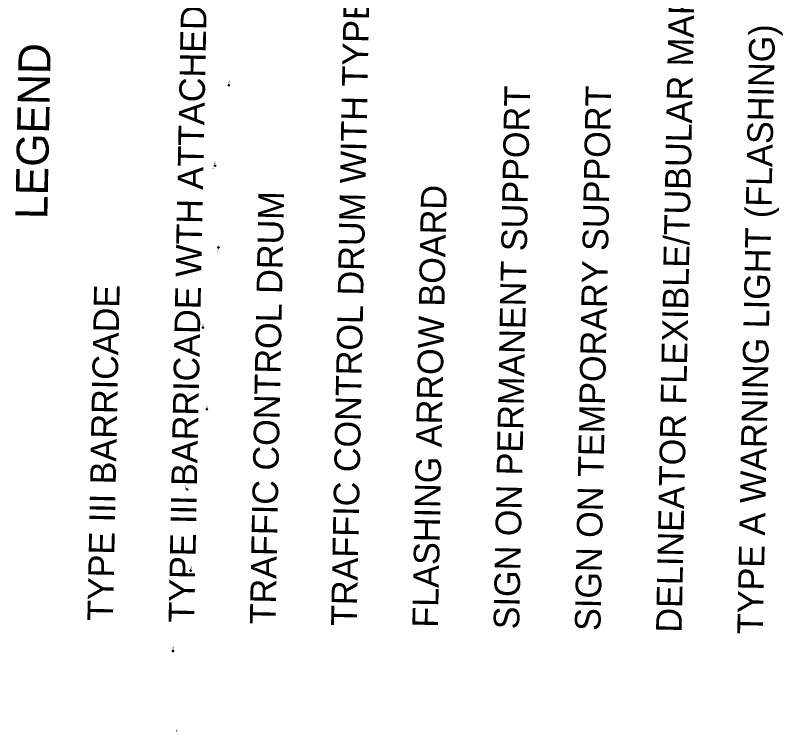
# Model space of a CAD drawing. Extents: x 345549 to 379569, y 127949 to 230467.
# Drawn here: x 358252 to 363918, y 165871 to 171164 of the extents above; entities that cross this region are included whole.
import ezdxf

# ---------------------------------------------------------------- set-up
doc = ezdxf.new("R2010")
doc.units = 0
for name, color, linetype in [('E_SOIL_BORE1 [KAPUR_CADDS_LEVELS]', 7, 'Continuous'), ('E_SOIL_BORE2 [KAPUR_CADDS_LEVELS]', 7, 'Continuous'), ('P_MARK', 7, 'Continuous'), ('P_TC_Text', 7, 'Continuous')]:
    doc.layers.add(name, color=color, linetype=linetype)

msp = doc.modelspace()

# ---------------------------------------------------------------- linework, layer by layer
at = {"layer": 'P_MARK'}
for p, q in [((359823, 170647.5), (359833, 170647.5)), ((359828, 170652.5), (359828, 170642.5)), ((359721.4, 170053), (359731.4, 170053)), ((359726.4, 170058), (359726.4, 170048)), ((359746.5, 169449.5), (359756.5, 169449.5)), ((359751.5, 169454.5), (359751.5, 169444.5)), ((359631.8, 168856.8), (359641.8, 168856.8)), ((359636.8, 168861.8), (359636.8, 168851.8)), ((359660.4, 168252.8), (359670.4, 168252.8)), ((359665.4, 168257.8), (359665.4, 168247.8)), ((359515.3, 167661.3), (359525.3, 167661.3)), ((359520.3, 167666.3), (359520.3, 167656.3)), ((359541.8, 167060.1), (359551.8, 167060.1)), ((359546.8, 167065.1), (359546.8, 167055.1)), ((359415, 166471.5), (359415, 166461.5)), ((359410, 166466.5), (359420, 166466.5))]:
    msp.add_line(p, q, dxfattribs=at)
for centre in [(359828, 170647.5), (359726.4, 170053), (359751.5, 169449.5), (359636.8, 168856.8), (359665.4, 168252.8), (359520.3, 167661.3), (359546.8, 167060.1), (359415, 166466.5)]:
    msp.add_circle(centre, 5, dxfattribs=at)
for centre, radius, start, end in [((359828, 170647.5), 4.5, 89.9869, 179.9869), ((359828, 170647.5), 4, 89.9869, 179.9869), ((359828, 170647.5), 3.5, 89.9869, 179.9869), ((359828, 170647.5), 3, 89.9869, 179.9869), ((359828, 170647.5), 2.5, 89.9869, 179.9869), ((359828, 170647.5), 2, 89.9869, 179.9869), ((359828, 170647.5), 1.5, 89.9869, 179.9869), ((359828, 170647.5), 1, 89.9869, 179.9869), ((359828, 170647.5), 0.5, 89.9869, 179.9869), ((359828, 170647.5), 4.5, 269.9869, 359.9869), ((359828, 170647.5), 4, 269.9869, 359.9869), ((359828, 170647.5), 3.5, 269.9869, 359.9869), ((359828, 170647.5), 3, 269.9869, 359.9869), ((359828, 170647.5), 2.5, 269.9869, 359.9869), ((359828, 170647.5), 2, 269.9869, 359.9869), ((359828, 170647.5), 1.5, 269.9869, 359.9869), ((359828, 170647.5), 1, 269.9869, 359.9869), ((359828, 170647.5), 0.5, 269.9869, 359.9869), ((359726.4, 170053), 4.5, 89.9869, 179.9869), ((359726.4, 170053), 4, 89.9869, 179.9869), ((359726.4, 170053), 3.5, 89.9869, 179.9869), ((359726.4, 170053), 3, 89.9869, 179.9869), ((359726.4, 170053), 2.5, 89.9869, 179.9869), ((359726.4, 170053), 2, 89.9869, 179.9869), ((359726.4, 170053), 1.5, 89.9869, 179.9869), ((359726.4, 170053), 1, 89.9869, 179.9869), ((359726.4, 170053), 0.5, 89.9869, 179.9869), ((359726.4, 170053), 4.5, 269.9869, 359.9869), ((359726.4, 170053), 4, 269.9869, 359.9869), ((359726.4, 170053), 3.5, 269.9869, 359.9869), ((359726.4, 170053), 3, 269.9869, 359.9869), ((359726.4, 170053), 2.5, 269.9869, 359.9869), ((359726.4, 170053), 2, 269.9869, 359.9869), ((359726.4, 170053), 1.5, 269.9869, 359.9869), ((359726.4, 170053), 1, 269.9869, 359.9869), ((359726.4, 170053), 0.5, 269.9869, 359.9869), ((359751.5, 169449.5), 4.5, 89.9869, 179.9869), ((359751.5, 169449.5), 4, 89.9869, 179.9869), ((359751.5, 169449.5), 3.5, 89.9869, 179.9869), ((359751.5, 169449.5), 3, 89.9869, 179.9869), ((359751.5, 169449.5), 2.5, 89.9869, 179.9869), ((359751.5, 169449.5), 2, 89.9869, 179.9869), ((359751.5, 169449.5), 1.5, 89.9869, 179.9869), ((359751.5, 169449.5), 1, 89.9869, 179.9869), ((359751.5, 169449.5), 0.5, 89.9869, 179.9869), ((359751.5, 169449.5), 4.5, 269.9869, 359.9869), ((359751.5, 169449.5), 4, 269.9869, 359.9869), ((359751.5, 169449.5), 3.5, 269.9869, 359.9869), ((359751.5, 169449.5), 3, 269.9869, 359.9869), ((359751.5, 169449.5), 2.5, 269.9869, 359.9869), ((359751.5, 169449.5), 2, 269.9869, 359.9869), ((359751.5, 169449.5), 1.5, 269.9869, 359.9869), ((359751.5, 169449.5), 1, 269.9869, 359.9869), ((359751.5, 169449.5), 0.5, 269.9869, 359.9869), ((359636.8, 168856.8), 4.5, 89.9869, 179.9869), ((359636.8, 168856.8), 4, 89.9869, 179.9869), ((359636.8, 168856.8), 3.5, 89.9869, 179.9869), ((359636.8, 168856.8), 3, 89.9869, 179.9869), ((359636.8, 168856.8), 2.5, 89.9869, 179.9869), ((359636.8, 168856.8), 2, 89.9869, 179.9869), ((359636.8, 168856.8), 1.5, 89.9869, 179.9869), ((359636.8, 168856.8), 1, 89.9869, 179.9869), ((359636.8, 168856.8), 0.5, 89.9869, 179.9869), ((359636.8, 168856.8), 4.5, 269.9869, 359.9869), ((359636.8, 168856.8), 4, 269.9869, 359.9869), ((359636.8, 168856.8), 3.5, 269.9869, 359.9869), ((359636.8, 168856.8), 3, 269.9869, 359.9869), ((359636.8, 168856.8), 2.5, 269.9869, 359.9869), ((359636.8, 168856.8), 2, 269.9869, 359.9869), ((359636.8, 168856.8), 1.5, 269.9869, 359.9869), ((359636.8, 168856.8), 1, 269.9869, 359.9869), ((359636.8, 168856.8), 0.5, 269.9869, 359.9869), ((359665.4, 168252.8), 4.5, 89.9869, 179.9869), ((359665.4, 168252.8), 4, 89.9869, 179.9869), ((359665.4, 168252.8), 3.5, 89.9869, 179.9869), ((359665.4, 168252.8), 3, 89.9869, 179.9869), ((359665.4, 168252.8), 2.5, 89.9869, 179.9869), ((359665.4, 168252.8), 2, 89.9869, 179.9869), ((359665.4, 168252.8), 1.5, 89.9869, 179.9869), ((359665.4, 168252.8), 1, 89.9869, 179.9869), ((359665.4, 168252.8), 0.5, 89.9869, 179.9869), ((359665.4, 168252.8), 4.5, 269.9869, 359.9869), ((359665.4, 168252.8), 4, 269.9869, 359.9869), ((359665.4, 168252.8), 3.5, 269.9869, 359.9869), ((359665.4, 168252.8), 3, 269.9869, 359.9869), ((359665.4, 168252.8), 2.5, 269.9869, 359.9869), ((359665.4, 168252.8), 2, 269.9869, 359.9869), ((359665.4, 168252.8), 1.5, 269.9869, 359.9869), ((359665.4, 168252.8), 1, 269.9869, 359.9869), ((359665.4, 168252.8), 0.5, 269.9869, 359.9869), ((359520.3, 167661.3), 4.5, 89.9869, 179.9869), ((359520.3, 167661.3), 4, 89.9869, 179.9869), ((359520.3, 167661.3), 3.5, 89.9869, 179.9869), ((359520.3, 167661.3), 3, 89.9869, 179.9869), ((359520.3, 167661.3), 2.5, 89.9869, 179.9869), ((359520.3, 167661.3), 2, 89.9869, 179.9869), ((359520.3, 167661.3), 1.5, 89.9869, 179.9869), ((359520.3, 167661.3), 1, 89.9869, 179.9869), ((359520.3, 167661.3), 0.5, 89.9869, 179.9869), ((359520.3, 167661.3), 4.5, 269.9869, 359.9869), ((359520.3, 167661.3), 4, 269.9869, 359.9869), ((359520.3, 167661.3), 3.5, 269.9869, 359.9869), ((359520.3, 167661.3), 3, 269.9869, 359.9869), ((359520.3, 167661.3), 2.5, 269.9869, 359.9869), ((359520.3, 167661.3), 2, 269.9869, 359.9869), ((359520.3, 167661.3), 1.5, 269.9869, 359.9869), ((359520.3, 167661.3), 1, 269.9869, 359.9869), ((359520.3, 167661.3), 0.5, 269.9869, 359.9869), ((359546.8, 167060.1), 4.5, 89.9869, 179.9869), ((359546.8, 167060.1), 4, 89.9869, 179.9869), ((359546.8, 167060.1), 3.5, 89.9869, 179.9869), ((359546.8, 167060.1), 3, 89.9869, 179.9869), ((359546.8, 167060.1), 2.5, 89.9869, 179.9869), ((359546.8, 167060.1), 2, 89.9869, 179.9869), ((359546.8, 167060.1), 1.5, 89.9869, 179.9869), ((359546.8, 167060.1), 1, 89.9869, 179.9869), ((359546.8, 167060.1), 0.5, 89.9869, 179.9869), ((359546.8, 167060.1), 4.5, 269.9869, 359.9869), ((359546.8, 167060.1), 4, 269.9869, 359.9869), ((359546.8, 167060.1), 3.5, 269.9869, 359.9869), ((359546.8, 167060.1), 3, 269.9869, 359.9869), ((359546.8, 167060.1), 2.5, 269.9869, 359.9869), ((359546.8, 167060.1), 2, 269.9869, 359.9869), ((359546.8, 167060.1), 1.5, 269.9869, 359.9869), ((359546.8, 167060.1), 1, 269.9869, 359.9869), ((359546.8, 167060.1), 0.5, 269.9869, 359.9869), ((359415, 166466.5), 4.5, 89.9869, 179.9869), ((359415, 166466.5), 4, 89.9869, 179.9869), ((359415, 166466.5), 3.5, 89.9869, 179.9869), ((359415, 166466.5), 3, 89.9869, 179.9869), ((359415, 166466.5), 2.5, 89.9869, 179.9869), ((359415, 166466.5), 2, 89.9869, 179.9869), ((359415, 166466.5), 1.5, 89.9869, 179.9869), ((359415, 166466.5), 1, 89.9869, 179.9869), ((359415, 166466.5), 0.5, 89.9869, 179.9869), ((359415, 166466.5), 4.5, 269.9869, 359.9869), ((359415, 166466.5), 4, 269.9869, 359.9869), ((359415, 166466.5), 3.5, 269.9869, 359.9869), ((359415, 166466.5), 3, 269.9869, 359.9869), ((359415, 166466.5), 2.5, 269.9869, 359.9869), ((359415, 166466.5), 2, 269.9869, 359.9869), ((359415, 166466.5), 1.5, 269.9869, 359.9869), ((359415, 166466.5), 1, 269.9869, 359.9869), ((359415, 166466.5), 0.5, 269.9869, 359.9869)]:
    msp.add_arc(centre, radius, start, end, dxfattribs=at)

# ---------------------------------------------------------------- texts
at = {"layer": 'E_SOIL_BORE1 [KAPUR_CADDS_LEVELS]'}
for s, p in [('B74', (359833.6, 170653.4)), ('B71', (359728.5, 170064.1)), ('B70', (359670.8, 168258.5)), ('B67', (359514.4, 167665.5)), ('B68', (359551.8, 167065.9))]:
    msp.add_text(s, height=10, rotation=84.1728, dxfattribs=at).set_placement(p)
at = {"layer": 'E_SOIL_BORE2 [KAPUR_CADDS_LEVELS]'}
for s, p in [('B71', (359719.2, 170026.7)), ('B72', (359753.1, 169417.7)), ('B69', (359641.9, 168864.4)), ('B65', (359420.1, 166473.6)), ('B66', (359448.3, 165869.7))]:
    msp.add_text(s, height=10, rotation=84.1728, dxfattribs=at).set_placement(p)
at = {"layer": 'P_TC_Text'}
for s, height, p in [('TRAFFIC CONTROL DRUM WITH TYPE C STEADY BURN LIGHT', 189, (360771.8, 166649.6)), ('TYPE III BARRICADE WTH ATTACHED SIGN', 189, (359572, 166673.8)), ('DELINEATOR FLEXIBLE/TUBULAR MARKER', 189, (363171.3, 166601.3)), ('TYPE A WARNING LIGHT (FLASHING)', 189, (363771.2, 166589.2)), ('LEGEND', 236.4, (358487.4, 169656.5)), ('SIGN ON PERMANENT SUPPORT', 189, (361971.5, 166625.5)), ('SIGN ON TEMPORARY SUPPORT', 189, (362571.4, 166613.4)), ('FLASHING ARROW BOARD', 189, (361371.7, 166637.6)), ('TRAFFIC CONTROL DRUM', 189, (360171.9, 166661.7)), ('TYPE III BARRICADE', 189, (358972.2, 166685.9))]:
    msp.add_text(s, height=height, rotation=88.8462, dxfattribs=at).set_placement(p)

doc.saveas('drawing.dxf')
